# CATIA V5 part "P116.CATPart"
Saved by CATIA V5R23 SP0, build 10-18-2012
Part number: P116
Definition: Rondelle ressort Ø 20.4 (bellville)
Description: Rondelle ressort Ø 20.4
Property "SUPPLIER": "NORELEM"
Property "REFERENCE": "NLM 07360-200"
Property "MATERIAL": "Acier à ressort"
Property "AUTHOR": "Trace Parts S.A."
Property "WEB": "www.traceparts.com"
Bounding box of the stored display mesh (mm): x -19.979 to 19.979, y -19.995 to 19.995, z 0 to 3.15
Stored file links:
  C:\wamp\www\COURS\CONCEPTION GMP1\TITRE 02-SEMESTRE 2\03-TP7-PRESSE MECANIQUE\eleve\P116.CATPart
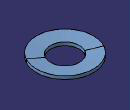
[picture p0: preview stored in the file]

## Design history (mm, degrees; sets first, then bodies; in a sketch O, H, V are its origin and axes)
Set1
  Point1: type Center, Curve edge [face of Solid1 | face of Solid1]
  Plane1: type OffsetPt, RefPlane xy-plane, RefPoint Point1
Body1 (main body)
  Solid1: solid without history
